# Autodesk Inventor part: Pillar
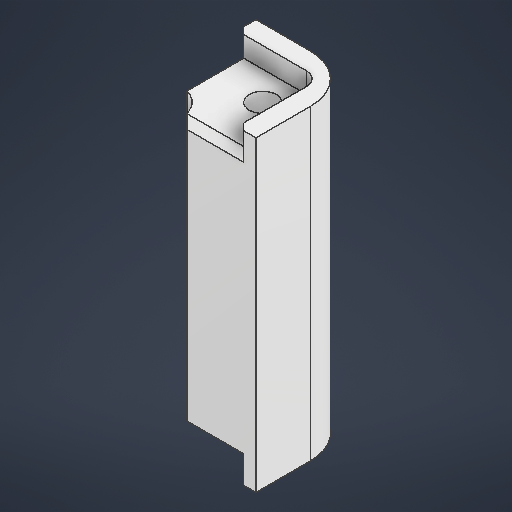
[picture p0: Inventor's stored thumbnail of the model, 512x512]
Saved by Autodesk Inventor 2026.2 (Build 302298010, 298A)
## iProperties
Created: 2026-04
Part Number: Pillar
Material: ABS 플라스틱
Document SubType Name: Modeling
Designer: work
Density: 1.06 g/cm^3
Appearance: 매끄러움 - 흰색
Author: work
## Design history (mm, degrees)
sketch "스케치1"
  geometry: L1 (0, 0)-(8, 0); L2 (0, 0)-(0, 8); L3 (8, 4)-(8, -7); L4 (8, -7)-(0, -7); L5 (8, 4)-(4, 4); L6 (4, 4)-(4, 8); L7 (4, 8)-(-7, 8); L8 (-7, 8)-(-7, 0); L9 (0, 0)-(-7, 0); L10 (0, 0)-(0, -7); C1 r 2 at (0, 0); A1 r 7 centre (0, 0) between (-7, 0) and (0, -7); 1 further point
  constraints: 20 end point, 3 perpendicular, 2 centre point, 2 horizontal, 2 point on circle, 2 point on line, 2 vertical, 1 coincident, 1 collinear, 1 concentric, 1 parallel, 1 tangent
  dimensions: "d0" = 4 diameter of C1; "d9" = 4 distance of L5.end L6.end; "d10" = 4 distance of L3.start L5.end; "d20" = 7 distance of L4.end point (0, 0); "d21" = 8 distance of L2.end point (0, 0); "d22" = 8 distance of L1.end point (0, 0)
extrude "돌출1" new body sketch "스케치1" distance "d11" = 45; taper "d12" = 0 deg
sketch "스케치2" dims "d23" = 4
  geometry: L1 (-4, -8)-(7, -8) reference; L2 (7, -8)-(7, 0) reference; L3 (0, 7)-(-8, 7) reference; L4 (-8, 7)-(-8, -4) reference; L5 (-8, -4)-(-4, -4) reference; L6 (-4, -4)-(-4, -8) reference; L7 (4.2, 2.2)-(4.2, -8); L8 (3.181, 4.2)-(-8, 4.2); C1 r 2 at (0, 0) reference; A1 r 7 centre (0, 0) between (7, 0) and (0, 7) reference; 2 further points
  constraints: 4 end point, 2 horizontal, 2 point on line, 1 perpendicular, 1 vertical, 3 other
  dimensions: "d24" = 2.8 distance between parallel lines of L2 L7; "d25" = 2.8 distance from line of L3.start L8
extrude "돌출2" cut sketch "스케치2" distance "d14" = 3; taper "d15" = 0 deg
node "작업 평면1"
fillet "모깎기1" dims "d16" = 4
chamfer "모따기1" distance "d17" = 1; stored, may be unused: second distance "d18" = 2, angle "d19" = 45 deg
node "솔리드1"
mirror "미러1"
node "투영된 루프1"
